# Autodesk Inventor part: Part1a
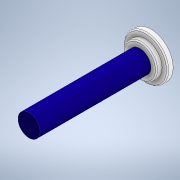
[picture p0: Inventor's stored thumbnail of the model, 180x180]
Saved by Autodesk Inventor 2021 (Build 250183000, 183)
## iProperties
Created: 2025-05
Part Number: Part1a
Material: Generic
Document SubType Name: Modeling
Designer: Aaditya
Density: 1 g/cm^3
Appearance: Default
Author: Aaditya
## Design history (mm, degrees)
sketch "Sketch1"
  geometry: C1 r 200 at (0, 0); 1 further point
  constraints: 1 centre point, 1 coincident
  dimensions: "d0" = 400 diameter of C1
extrude "Extrusion1" new body sketch "Sketch1" distance "d1" = 50; taper "d2" = 0 deg
sketch "Sketch2"
  geometry: C1 r 150 at (0, 0); 1 further point
  constraints: 1 centre point, 1 coincident
  dimensions: "d3" = 300 diameter of C1
extrude "Extrusion2" join sketch "Sketch2" distance "d4" = 50; taper "d5" = 0 deg
fillet "Fillet1" dims "d12" = 10
sketch "Sketch5"
  geometry: C1 r 100 at (0, 0); 1 further point
  constraints: 1 centre point, 1 coincident
  dimensions: "d13" = 200 diameter of C1
extrude "Extrusion5" join sketch "Sketch5" distance "d14" = 1000; taper "d15" = 0 deg
body "Solid1"
